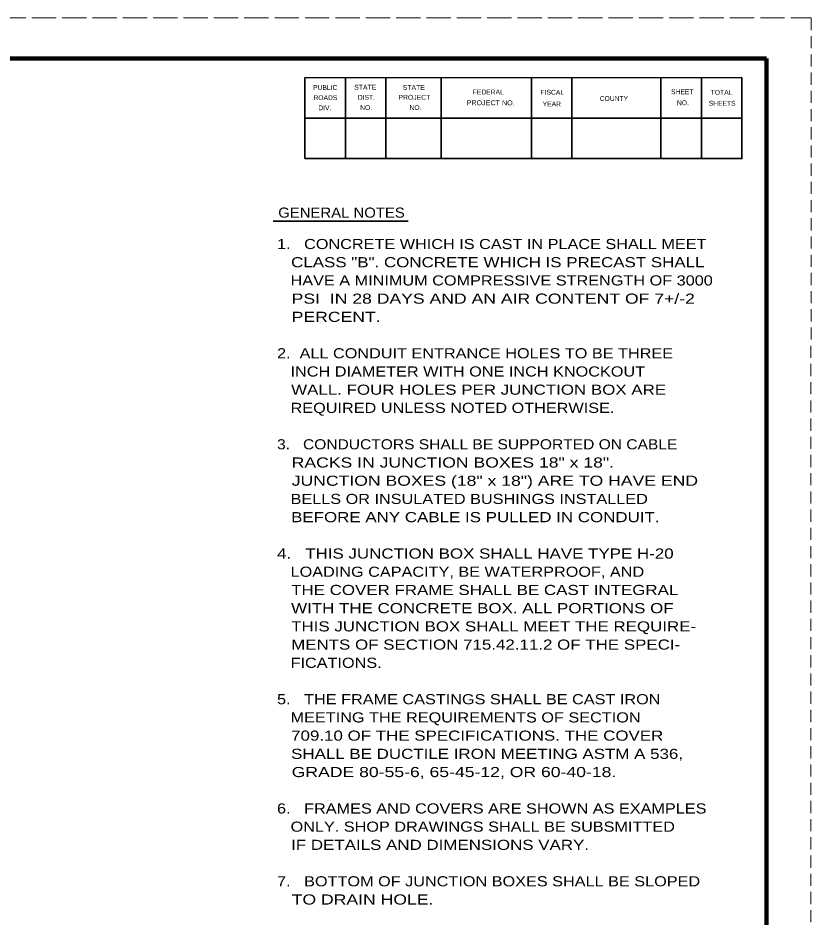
# Model space of a CAD drawing. Extents: x 788 to 1469, y -1 to 439.
# Drawn here: x 1272.6 to 1468.5, y 216.9 to 439.1 of the extents above; entities that cross this region are included whole.
import ezdxf

# ---------------------------------------------------------------- set-up
doc = ezdxf.new("R2010")
doc.units = 0
doc.linetypes.add('LONG_DASHED', pattern=[7.5, 6, -1.5])
doc.linetypes.add('MEDIUM_DASHED', pattern=[4.5, 3, -1.5])
doc.layers.add('1', color=7, linetype='Continuous', lineweight=35)
doc.layers.add('61', color=7, linetype='Continuous', lineweight=35)

msp = doc.modelspace()

# ---------------------------------------------------------------- linework, layer by layer
at = {"layer": '1', "linetype": 'MEDIUM_DASHED', "lineweight": 13}
msp.add_line((1468.547, 439.076), (1468.527, -0.944), dxfattribs=at)
at = {"layer": '1'}
msp.add_line((1335.682, 388.848), (1368.982, 388.848), dxfattribs=at)
at = {"layer": '61', "linetype": 'LONG_DASHED', "lineweight": 13}
msp.add_line((788.527, 439.076), (1468.547, 439.076), dxfattribs=at)
at = {"layer": '61', "lineweight": 158}
msp.add_line((1457.567, 429.076), (1457.587, 9.036), dxfattribs=at)
at = {"layer": '61'}
for p, q in [((1353.487, 424.316), (1353.487, 404.316)), ((1363.487, 424.316), (1363.487, 404.316)), ((1377.167, 424.316), (1377.167, 404.316)), ((1399.487, 424.316), (1399.487, 404.316)), ((1409.487, 424.316), (1409.487, 404.316)), ((1431.467, 424.336), (1431.467, 404.336)), ((1441.467, 424.336), (1441.467, 404.336)), ((1451.487, 414.296), (1343.467, 414.316))]:
    msp.add_line(p, q, dxfattribs=at)
at = {"layer": '61', "lineweight": 158}
msp.add_lwpolyline([(1457.567, 429.076), (818.527, 429.076), (818.527, 9.056)], dxfattribs=at)
at = {"layer": '61'}
for points in [[(1451.467, 424.336), (1343.487, 424.316), (1343.487, 404.316)], [(1451.467, 424.336), (1451.467, 404.336), (1343.487, 404.316)]]:
    msp.add_lwpolyline(points, dxfattribs=at)

# ---------------------------------------------------------------- texts
at = {"layer": '1'}
for s, width, p in [('GENERAL NOTES', 1.1, (1336.909, 389.724)), ('1.   CONCRETE WHICH IS CAST IN PLACE SHALL MEET', 1.2, (1336.609, 381.962)), ('   CLASS "B". CONCRETE WHICH IS PRECAST SHALL', 1.25, (1336.609, 377.462)), ('   HAVE A MINIMUM COMPRESSIVE STRENGTH OF 3000', 1.2, (1336.609, 372.962)), ('   PSI  IN 28 DAYS AND AN AIR CONTENT OF 7+/-2', 1.3, (1336.609, 368.462)), ('   PERCENT.', 1.3, (1336.609, 363.962)), ('2.  ALL CONDUIT ENTRANCE HOLES TO BE THREE', 1.2, (1336.609, 354.962)), ('   INCH DIAMETER WITH ONE INCH KNOCKOUT', 1.2, (1336.609, 350.462)), ('   WALL. FOUR HOLES PER JUNCTION BOX ARE', 1.25, (1336.609, 345.962)), ('   REQUIRED UNLESS NOTED OTHERWISE.', 1.2, (1336.609, 341.462)), ('3.   CONDUCTORS SHALL BE SUPPORTED ON CABLE', 1.15, (1336.609, 332.462)), ('   RACKS IN JUNCTION BOXES 18" x 18".', 1.3, (1336.609, 327.962)), ('   JUNCTION BOXES (18" x 18") ARE TO HAVE END', 1.3, (1336.609, 323.462)), ('   BELLS OR INSULATED BUSHINGS INSTALLED', 1.2, (1336.609, 318.962)), ('   BEFORE ANY CABLE IS PULLED IN CONDUIT.', 1.25, (1336.609, 314.462)), ('4.   THIS JUNCTION BOX SHALL HAVE TYPE H-20', 1.25, (1336.609, 305.462)), ('   LOADING CAPACITY, BE WATERPROOF, AND', 1.2, (1336.609, 300.962)), ('   THE COVER FRAME SHALL BE CAST INTEGRAL', 1.25, (1336.609, 296.462)), ('   WITH THE CONCRETE BOX. ALL PORTIONS OF', 1.25, (1336.609, 291.962)), ('   THIS JUNCTION BOX SHALL MEET THE REQUIRE-', 1.25, (1336.609, 287.462)), ('   MENTS OF SECTION 715.42.11.2 OF THE SPECI-', 1.25, (1336.609, 282.962)), ('   FICATIONS.', 1.2, (1336.609, 278.462)), ('5.   THE FRAME CASTINGS SHALL BE CAST IRON', 1.2, (1336.609, 269.462)), ('   MEETING THE REQUIREMENTS OF SECTION', 1.2, (1336.609, 264.962)), ('   709.10 OF THE SPECIFICATIONS. THE COVER', 1.25, (1336.609, 260.462)), ('   SHALL BE DUCTILE IRON MEETING ASTM A 536,', 1.25, (1336.609, 255.962)), ('   GRADE 80-55-6, 65-45-12, OR 60-40-18.', 1.3, (1336.609, 251.462)), ('6.   FRAMES AND COVERS ARE SHOWN AS EXAMPLES', 1.2, (1336.609, 242.462)), ('   ONLY. SHOP DRAWINGS SHALL BE SUBSMITTED', 1.2, (1336.609, 237.962)), ('   IF DETAILS AND DIMENSIONS VARY.', 1.25, (1336.609, 233.462)), ('7.   BOTTOM OF JUNCTION BOXES SHALL BE SLOPED', 1.2, (1336.609, 224.462)), ('   TO DRAIN HOLE.', 1.3, (1336.609, 219.962))]:
    msp.add_text(s, height=2.5, dxfattribs=dict(at, width=width)).set_placement(p)
at = {"layer": '61'}
for s, rotation, p in [('PUBLIC', 0.033, (1345.527, 421.296)), ('ROADS', 0.124, (1345.607, 418.776)), ('DIST.', 0.056, (1356.567, 418.856)), ('FEDERAL', 0.007, (1384.987, 420.176)), ('FISCAL', 359.942, (1401.727, 420.116)), ('SHEET', 0.059, (1433.987, 420.236)), ('YEAR', 0.105, (1402.247, 417.216)), ('COUNTY', 0.069, (1416.347, 418.576)), ('SHEETS', 359.959, (1443.267, 417.396)), ('DIV.', 359.932, (1346.807, 416.276))]:
    msp.add_text(s, height=1.201, rotation=rotation, dxfattribs=at).set_placement(p)
for s, rotation, width, p in [('STATE', 0.059, 1.05, (1355.687, 421.356)), ('STATE', 0.059, 1.05, (1367.687, 421.296)), ('PROJECT', 359.908, 1.05, (1366.607, 418.876)), ('TOTAL', 359.926, 1.05, (1443.727, 420.096)), ('PROJECT NO.', 359.922, 1.1, (1383.447, 417.516)), ('NO.', 359.852, 0.95, (1435.407, 417.516)), ('NO.', 359.852, 0.95, (1357.147, 416.336)), ('NO.', 0.225, 0.95, (1369.347, 416.336))]:
    msp.add_text(s, height=1.201, rotation=rotation, dxfattribs=dict(at, width=width)).set_placement(p)

doc.saveas('drawing.dxf')
